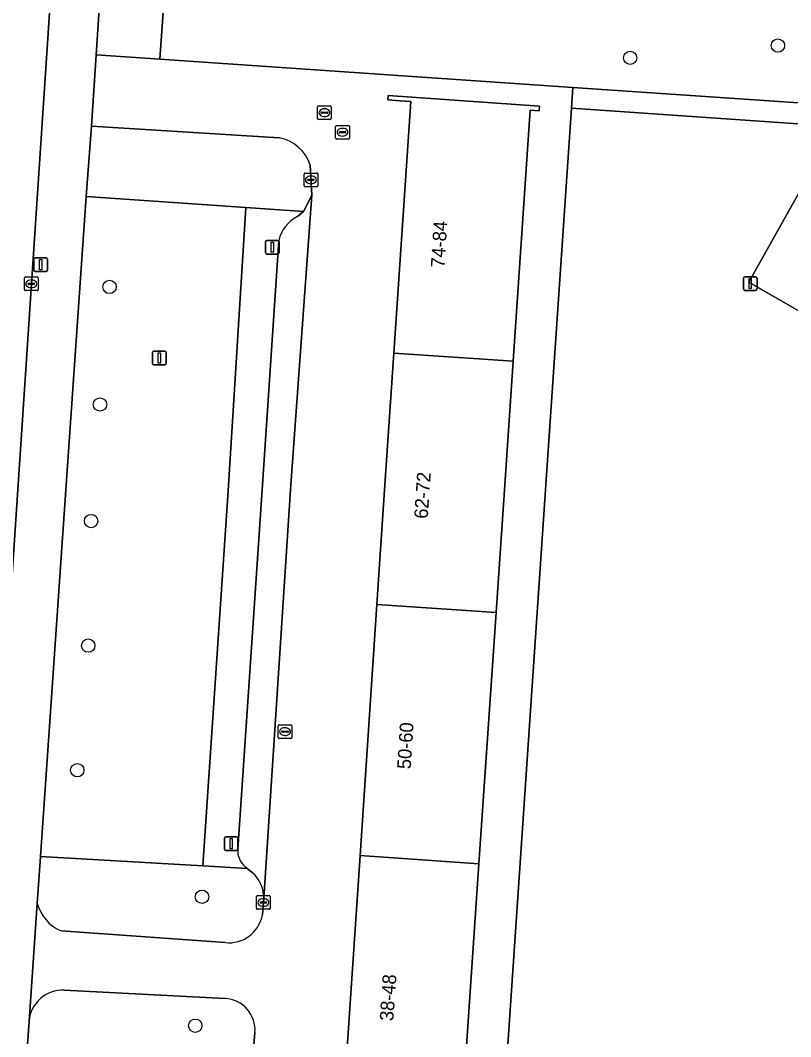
# Model space of a CAD drawing. Extents: x 161848 to 162726, y 385382 to 386521.
# Drawn here: x 162445.2 to 162501.6, y 385460 to 385534.3 of the extents above; entities that cross this region are included whole.
import ezdxf

# ---------------------------------------------------------------- set-up
doc = ezdxf.new("R2010")
doc.units = 0
for name, color, linetype in [('IMGEO_Boom', 7, 'Continuous'), ('IMGEO_Brandkraan', 7, 'Continuous'), ('IMGEO_Groenvoorziening', 7, 'Continuous'), ('IMGEO_Kolk', 7, 'Continuous'), ('IMGEO_Lichtmast', 7, 'Continuous'), ('IMGEO_Pand', 7, 'Continuous'), ('IMGEO_Pand_nummerreeks', 7, 'Continuous'), ('IMGEO_Parkeervlak_open', 7, 'Continuous'), ('IMGEO_Rijbaan_lokaal_gesloten', 7, 'Continuous'), ('IMGEO_Rijbaan_lokaal_open', 7, 'Continuous'), ('IMGEO_Rioolput', 7, 'Continuous'), ('IMGEO_Terreindeel_zand', 7, 'Continuous'), ('IMGEO_Verkeersbordpaal', 7, 'Continuous'), ('IMGEO_Voetpad_open', 7, 'Continuous')]:
    doc.layers.add(name, color=color, linetype=linetype)

msp = doc.modelspace()

# ---------------------------------------------------------------- linework, layer by layer
at = {"layer": 'IMGEO_Boom'}
for centre in [(162500.623, 385532.496), (162489.82, 385531.597), (162451.736, 385514.843), (162451.036, 385506.243), (162450.384, 385497.718), (162450.172, 385488.607), (162449.375, 385479.496), (162458.499, 385470.237), (162458.007, 385460.808)]:
    msp.add_circle(centre, 0.489, dxfattribs=at)
at = {"layer": 'IMGEO_Brandkraan'}
for p, q in [((162468.276, 385525.731), (162468.276, 385526.583)), ((162468.351, 385526.657), (162469.203, 385526.657)), ((162469.277, 385526.583), (162469.277, 385525.731)), ((162468.535, 385526.151), (162468.535, 385526.163)), ((162468.973, 385526.114), (162468.575, 385526.114)), ((162468.578, 385526.2), (162468.976, 385526.2)), ((162468.787, 385525.877), (162468.762, 385525.877)), ((162468.764, 385526.437), (162468.789, 385526.437)), ((162469.019, 385526.163), (162469.019, 385526.151)), ((162469.203, 385525.657), (162468.351, 385525.657))]:
    msp.add_line(p, q, dxfattribs=at)
for points in [[(162468.276, 385525.731), (162468.276, 385526.583)], [(162468.351, 385526.657), (162469.203, 385526.657)], [(162469.277, 385526.583), (162469.277, 385525.731)], [(162469.203, 385525.657), (162468.351, 385525.657)]]:
    msp.add_lwpolyline(points, dxfattribs=at)
for centre, radius, start, end in [((162468.353, 385526.581), 0.0765, 91.55205, 178.44795), ((162468.353, 385526.581), 0.0765, 91.55205, 178.44795), ((162469.201, 385526.581), 0.0765, 1.55205, 88.44795), ((162469.201, 385526.581), 0.0765, 1.55205, 88.44795), ((162468.575, 385526.16), 0.0403, 85.87752, 175.75265), ((162468.572, 385526.15), 0.0366, 178.93798, 274.71019), ((162468.976, 385526.157), 0.043, 264.86636, 352.45326), ((162468.98, 385526.162), 0.0386, 1.73085, 96.63898), ((162468.353, 385525.733), 0.0765, 181.55205, 268.44795), ((162468.353, 385525.733), 0.0765, 181.55205, 268.44795), ((162469.201, 385525.733), 0.0765, 271.55205, 358.44795), ((162469.201, 385525.733), 0.0765, 271.55205, 358.44795)]:
    msp.add_arc(centre, radius, start, end, dxfattribs=at)
for centre, major_axis, ratio, start_param, end_param in [((162468.763, 385526.157), (-0.387, 0.002), 0.722429, 4.712389, 7.853982), ((162468.788, 385526.157), (-0.39, 0.002), 0.717154, 1.570796, 4.712389)]:
    msp.add_ellipse(centre, major_axis=major_axis, ratio=ratio, start_param=start_param, end_param=end_param, dxfattribs=at)
at = {"layer": 'IMGEO_Groenvoorziening'}
for points in [[(162454.648, 385591.147), (162452.933, 385565.323), (162452.649, 385560.747), (162450.744, 385531.817), (162455.419, 385531.5), (162457.472, 385560.354), (162457.863, 385565.85), (162459.643, 385590.86), (162456.232, 385592.147)], [(162457.472, 385560.354), (162455.419, 385531.5), (162485.619, 385529.433), (162500, 385528.449), (162507.432, 385527.947), (162530.647, 385526.38), (162533.646, 385526.394)], [(162545.914, 385523.54), (162543.337, 385523.731), (162511.005, 385526.131), (162512.576, 385525.273), (162511.727, 385523.716), (162517.465, 385520.441), (162510.579, 385508.238), (162498.496, 385515.202), (162504.878, 385526.574), (162500, 385526.911), (162485.517, 385527.913), (162483.623, 385500), (162482.431, 385482.424), (162476.506, 385395.087), (162488.091, 385395.556), (162488.621, 385396.589)], [(162464.139, 385525.753), (162450.405, 385526.588), (162450.031, 385521.458), (162461.707, 385520.661), (162465.911, 385520.366), (162466.531, 385521.555), (162466.414, 385523.772)], [(162465.488, 385519.982), (162465.911, 385520.366), (162461.707, 385520.661), (162460.415, 385499.937), (162458.56, 385472.499), (162461.807, 385472.309), (162461.663, 385472.429)], [(162461.109, 385473.721), (162462.89, 385500), (162464.126, 385518.245)], [(162462.157, 385472.017), (162461.807, 385472.309), (162458.56, 385472.499), (162446.676, 385473.196), (162446.446, 385469.756)], [(162462.922, 385468.908), (162463.011, 385470.132)], [(162448.204, 385467.741), (162460.195, 385466.883)], [(162460.188, 385462.798), (162448.404, 385463.41)], [(162445.849, 385461.151), (162445.688, 385458.726), (162458.022, 385457.834), (162461.314, 385457.562)], [(162462.277, 385459.102), (162462.37, 385460.301)]]:
    msp.add_lwpolyline(points, dxfattribs=at)
msp.add_lwpolyline([(162448.539, 385500), (162446.676, 385473.196), (162458.56, 385472.499), (162460.415, 385499.937), (162461.707, 385520.661), (162450.031, 385521.458)], close=True, dxfattribs=at)
for centre, radius, start, end in [((162463.578, 385522.811), 2.995, 18.70946, 79.19385), ((162466.556, 385517.742), 2.481, 115.49056, 168.3087), ((162462.653, 385473.618), 1.547, 176.19189, 230.22669), ((162460.634, 385470.191), 2.377, 358.57248, 50.17336), ((162449.348, 385470.513), 2.999, 194.62338, 247.58319), ((162460.457, 385469.379), 2.51, 264.01062, 349.18264), ((162448.302, 385460.951), 2.461, 87.62337, 175.33956), ((162460.069, 385460.492), 2.309, 355.2525, 87.04458)]:
    msp.add_arc(centre, radius, start, end, dxfattribs=at)
at = {"layer": 'IMGEO_Kolk'}
for p, q in [((162465.967, 385522.246), (162465.967, 385523.098)), ((162466.042, 385523.172), (162466.894, 385523.172)), ((162466.455, 385522.952), (162466.48, 385522.952)), ((162466.968, 385523.098), (162466.968, 385522.246)), ((162466.894, 385522.172), (162466.042, 385522.172)), ((162466.226, 385522.666), (162466.226, 385522.678)), ((162466.664, 385522.629), (162466.266, 385522.629)), ((162466.269, 385522.715), (162466.667, 385522.715)), ((162466.478, 385522.392), (162466.453, 385522.392)), ((162466.71, 385522.678), (162466.71, 385522.666)), ((162445.508, 385514.644), (162445.508, 385515.496)), ((162445.583, 385515.57), (162446.435, 385515.57)), ((162446.509, 385515.496), (162446.509, 385514.644)), ((162445.767, 385515.064), (162445.767, 385515.076)), ((162446.205, 385515.027), (162445.807, 385515.027)), ((162445.81, 385515.113), (162446.208, 385515.113)), ((162446.019, 385514.79), (162445.994, 385514.79)), ((162445.996, 385515.35), (162446.021, 385515.35)), ((162446.251, 385515.076), (162446.251, 385515.064)), ((162446.435, 385514.57), (162445.583, 385514.57)), ((162462.486, 385469.395), (162462.486, 385470.247)), ((162462.561, 385470.321), (162463.413, 385470.321)), ((162462.974, 385470.101), (162462.999, 385470.101)), ((162463.487, 385470.247), (162463.487, 385469.395)), ((162463.413, 385469.321), (162462.561, 385469.321)), ((162462.745, 385469.815), (162462.745, 385469.827)), ((162463.183, 385469.778), (162462.785, 385469.778)), ((162462.788, 385469.864), (162463.186, 385469.864)), ((162462.997, 385469.541), (162462.972, 385469.541)), ((162463.229, 385469.827), (162463.229, 385469.815))]:
    msp.add_line(p, q, dxfattribs=at)
for points in [[(162465.967, 385522.246), (162465.967, 385523.098)], [(162466.042, 385523.172), (162466.894, 385523.172)], [(162466.968, 385523.098), (162466.968, 385522.246)], [(162466.894, 385522.172), (162466.042, 385522.172)], [(162445.508, 385514.644), (162445.508, 385515.496)], [(162445.583, 385515.57), (162446.435, 385515.57)], [(162446.509, 385515.496), (162446.509, 385514.644)], [(162446.435, 385514.57), (162445.583, 385514.57)], [(162462.486, 385469.395), (162462.486, 385470.247)], [(162462.561, 385470.321), (162463.413, 385470.321)], [(162463.487, 385470.247), (162463.487, 385469.395)], [(162463.413, 385469.321), (162462.561, 385469.321)]]:
    msp.add_lwpolyline(points, dxfattribs=at)
for centre, radius, start, end in [((162466.044, 385523.096), 0.0765, 91.55205, 178.44795), ((162466.044, 385523.096), 0.0765, 91.55205, 178.44795), ((162466.892, 385523.096), 0.0765, 1.55205, 88.44795), ((162466.892, 385523.096), 0.0765, 1.55205, 88.44795), ((162466.044, 385522.248), 0.0765, 181.55205, 268.44795), ((162466.044, 385522.248), 0.0765, 181.55205, 268.44795), ((162466.266, 385522.675), 0.0403, 85.87752, 175.75265), ((162466.263, 385522.665), 0.0366, 178.93798, 274.71019), ((162466.667, 385522.672), 0.043, 264.86636, 352.45326), ((162466.671, 385522.677), 0.0386, 1.73085, 96.63898), ((162466.892, 385522.248), 0.0765, 271.55205, 358.44795), ((162466.892, 385522.248), 0.0765, 271.55205, 358.44795), ((162445.585, 385515.494), 0.0765, 91.55205, 178.44795), ((162445.585, 385515.494), 0.0765, 91.55205, 178.44795), ((162446.433, 385515.494), 0.0765, 1.55205, 88.44795), ((162446.433, 385515.494), 0.0765, 1.55205, 88.44795), ((162445.585, 385514.646), 0.0765, 181.55205, 268.44795), ((162445.585, 385514.646), 0.0765, 181.55205, 268.44795), ((162445.807, 385515.073), 0.0403, 85.87752, 175.75265), ((162445.804, 385515.063), 0.0366, 178.93798, 274.71019), ((162446.208, 385515.07), 0.043, 264.86636, 352.45326), ((162446.212, 385515.075), 0.0386, 1.73085, 96.63898), ((162446.433, 385514.646), 0.0765, 271.55205, 358.44795), ((162446.433, 385514.646), 0.0765, 271.55205, 358.44795), ((162462.563, 385470.245), 0.0765, 91.55205, 178.44795), ((162462.563, 385470.245), 0.0765, 91.55205, 178.44795), ((162463.411, 385470.245), 0.0765, 1.55205, 88.44795), ((162463.411, 385470.245), 0.0765, 1.55205, 88.44795), ((162462.563, 385469.397), 0.0765, 181.55205, 268.44795), ((162462.563, 385469.397), 0.0765, 181.55205, 268.44795), ((162462.785, 385469.824), 0.0403, 85.87752, 175.75265), ((162462.782, 385469.814), 0.0366, 178.93798, 274.71019), ((162463.186, 385469.821), 0.043, 264.86636, 352.45326), ((162463.19, 385469.826), 0.0386, 1.73085, 96.63898), ((162463.411, 385469.397), 0.0765, 271.55205, 358.44795), ((162463.411, 385469.397), 0.0765, 271.55205, 358.44795)]:
    msp.add_arc(centre, radius, start, end, dxfattribs=at)
for centre, major_axis, ratio, start_param, end_param in [((162466.454, 385522.672), (-0.387, 0.002), 0.722429, 4.712389, 7.853982), ((162466.479, 385522.672), (-0.39, 0.002), 0.717154, 1.570796, 4.712389), ((162445.995, 385515.07), (-0.387, 0.002), 0.722429, 4.712389, 7.853982), ((162446.02, 385515.07), (-0.39, 0.002), 0.717154, 1.570796, 4.712389), ((162462.973, 385469.821), (-0.387, 0.002), 0.722429, 4.712389, 7.853982), ((162462.998, 385469.821), (-0.39, 0.002), 0.717154, 1.570796, 4.712389)]:
    msp.add_ellipse(centre, major_axis=major_axis, ratio=ratio, start_param=start_param, end_param=end_param, dxfattribs=at)
at = {"layer": 'IMGEO_Lichtmast'}
for p, q in [((162463.148, 385517.348), (162463.148, 385518.148)), ((162463.148, 385518.148), (162463.148, 385517.348)), ((162463.248, 385518.248), (162464.038, 385518.248)), ((162464.038, 385518.248), (162463.248, 385518.248)), ((162464.138, 385518.148), (162464.138, 385517.348)), ((162464.138, 385517.348), (162464.138, 385518.148)), ((162446.201, 385516.062), (162446.201, 385516.862)), ((162446.201, 385516.862), (162446.201, 385516.062)), ((162446.301, 385516.962), (162447.091, 385516.962)), ((162447.091, 385516.962), (162446.301, 385516.962)), ((162447.191, 385516.862), (162447.191, 385516.062)), ((162447.191, 385516.062), (162447.191, 385516.862)), ((162464.038, 385517.248), (162463.248, 385517.248)), ((162463.248, 385517.248), (162464.038, 385517.248)), ((162447.091, 385515.962), (162446.301, 385515.962)), ((162446.301, 385515.962), (162447.091, 385515.962)), ((162460.139, 385473.723), (162460.139, 385474.523)), ((162460.139, 385474.523), (162460.139, 385473.723)), ((162460.239, 385474.623), (162461.029, 385474.623)), ((162461.029, 385474.623), (162460.239, 385474.623)), ((162461.129, 385474.523), (162461.129, 385473.723)), ((162461.129, 385473.723), (162461.129, 385474.523)), ((162461.029, 385473.623), (162460.239, 385473.623)), ((162460.239, 385473.623), (162461.029, 385473.623))]:
    msp.add_line(p, q, dxfattribs=at)
for points in [[(162463.568, 385518.123), (162463.718, 385518.123), (162463.718, 385517.373), (162463.568, 385517.373), (162463.568, 385518.123)], [(162446.621, 385516.837), (162446.771, 385516.837), (162446.771, 385516.087), (162446.621, 385516.087), (162446.621, 385516.837)], [(162460.559, 385474.498), (162460.709, 385474.498), (162460.709, 385473.748), (162460.559, 385473.748), (162460.559, 385474.498)]]:
    msp.add_lwpolyline(points, dxfattribs=at)
for centre, start, end in [((162463.248, 385518.148), 90, 180), ((162463.248, 385518.148), 90, 180), ((162464.038, 385518.148), 0, 90), ((162464.038, 385518.148), 360, 90), ((162446.301, 385516.862), 90, 180), ((162446.301, 385516.862), 90, 180), ((162447.091, 385516.862), 0, 90), ((162447.091, 385516.862), 360, 90), ((162463.248, 385517.348), 180, 270), ((162463.248, 385517.348), 180, 270), ((162464.038, 385517.348), 270, 0), ((162464.038, 385517.348), 270, 0), ((162446.301, 385516.062), 180, 270), ((162446.301, 385516.062), 180, 270), ((162447.091, 385516.062), 270, 0), ((162447.091, 385516.062), 270, 0), ((162460.239, 385474.523), 90, 180), ((162460.239, 385474.523), 90, 180), ((162461.029, 385474.523), 0, 90), ((162461.029, 385474.523), 360, 90), ((162460.239, 385473.723), 180, 270), ((162460.239, 385473.723), 180, 270), ((162461.029, 385473.723), 270, 0), ((162461.029, 385473.723), 270, 0)]:
    msp.add_arc(centre, 0.1, start, end, dxfattribs=at)
at = {"layer": 'IMGEO_Pand'}
for points in [[(162473.772, 385528.397), (162472.532, 385509.995), (162481.258, 385509.402), (162482.508, 385527.775), (162483.158, 385527.73), (162483.182, 385528.074), (162472.117, 385528.841), (162472.095, 385528.514), (162472.999, 385528.451)], [(162471.859, 385500), (162471.295, 385491.621), (162480.009, 385491.029), (162480.619, 385500), (162481.258, 385509.402), (162472.532, 385509.995)], [(162470.057, 385473.247), (162478.76, 385472.656), (162480.009, 385491.029), (162471.295, 385491.621)], [(162468.819, 385454.873), (162477.51, 385454.282), (162478.76, 385472.656), (162470.057, 385473.247)]]:
    msp.add_lwpolyline(points, close=True, dxfattribs=at)
at = {"layer": 'IMGEO_Parkeervlak_open'}
for points in [[(162463.011, 385470.132), (162464.984, 385500), (162465.008, 385500.369), (162466.531, 385521.555), (162465.911, 385520.366), (162465.488, 385519.982)], [(162464.126, 385518.245), (162462.89, 385500), (162461.109, 385473.721)], [(162461.663, 385472.429), (162461.807, 385472.309), (162462.157, 385472.017)]]:
    msp.add_lwpolyline(points, dxfattribs=at)
for centre, radius, start, end in [((162466.556, 385517.742), 2.481, 115.49056, 168.3087), ((162462.653, 385473.618), 1.547, 176.19189, 230.22669), ((162460.634, 385470.191), 2.377, 358.57248, 50.17336)]:
    msp.add_arc(centre, radius, start, end, dxfattribs=at)
at = {"layer": 'IMGEO_Rijbaan_lokaal_gesloten'}
msp.add_lwpolyline([(162442.399, 385460.482), (162442.465, 385461.839), (162450.162, 385577.468)], dxfattribs=at)
at = {"layer": 'IMGEO_Rijbaan_lokaal_open'}
for points in [[(162482.431, 385482.424), (162483.623, 385500), (162485.517, 385527.913), (162485.619, 385529.433), (162455.419, 385531.5), (162450.744, 385531.817), (162450.405, 385526.588), (162464.139, 385525.753)], [(162466.414, 385523.772), (162466.531, 385521.555), (162465.008, 385500.369), (162464.984, 385500), (162463.011, 385470.132), (162462.922, 385468.908)], [(162462.37, 385460.301), (162462.277, 385459.102), (162462.235, 385458.558), (162458.175, 385399.31), (162457.836, 385394.534), (162462.968, 385394.635), (162463.18, 385398.467), (162475.007, 385397.387), (162474.868, 385395.02), (162476.506, 385395.087), (162482.431, 385482.424)], [(162446.446, 385469.756), (162445.849, 385461.151)], [(162460.195, 385466.883), (162448.204, 385467.741)], [(162448.404, 385463.41), (162460.188, 385462.798)]]:
    msp.add_lwpolyline(points, dxfattribs=at)
msp.add_lwpolyline([(162470.057, 385473.247), (162471.295, 385491.621), (162471.859, 385500), (162472.532, 385509.995), (162473.772, 385528.397), (162472.999, 385528.451), (162472.095, 385528.514), (162472.117, 385528.841), (162483.182, 385528.074), (162483.158, 385527.73), (162482.508, 385527.775), (162481.258, 385509.402), (162480.619, 385500), (162480.009, 385491.029), (162478.76, 385472.656), (162477.51, 385454.282), (162476.261, 385435.909), (162475.011, 385417.536), (162473.762, 385399.163), (162465.106, 385399.742), (162466.344, 385418.126), (162467.582, 385436.499), (162468.819, 385454.873)], close=True, dxfattribs=at)
for centre, radius, start, end in [((162463.578, 385522.811), 2.995, 18.70946, 79.19385), ((162449.348, 385470.513), 2.999, 194.62338, 247.58319), ((162460.457, 385469.379), 2.51, 264.01062, 349.18264), ((162448.302, 385460.951), 2.461, 87.62337, 175.33956), ((162460.069, 385460.492), 2.309, 355.2525, 87.04458)]:
    msp.add_arc(centre, radius, start, end, dxfattribs=at)
at = {"layer": 'IMGEO_Rioolput'}
for p, q in [((162466.955, 385527.16), (162466.955, 385528.012)), ((162467.03, 385528.086), (162467.882, 385528.086)), ((162467.956, 385528.012), (162467.956, 385527.16)), ((162467.214, 385527.58), (162467.214, 385527.592)), ((162467.652, 385527.543), (162467.254, 385527.543)), ((162467.257, 385527.629), (162467.655, 385527.629)), ((162467.466, 385527.306), (162467.441, 385527.306)), ((162467.443, 385527.866), (162467.468, 385527.866)), ((162467.698, 385527.592), (162467.698, 385527.58)), ((162467.882, 385527.086), (162467.03, 385527.086)), ((162464.073, 385481.89), (162464.073, 385482.742)), ((162464.148, 385482.816), (162465, 385482.816)), ((162465.074, 385482.742), (162465.074, 385481.89)), ((162464.332, 385482.31), (162464.332, 385482.322)), ((162464.77, 385482.273), (162464.372, 385482.273)), ((162464.375, 385482.359), (162464.773, 385482.359)), ((162464.584, 385482.036), (162464.559, 385482.036)), ((162464.561, 385482.596), (162464.586, 385482.596)), ((162464.816, 385482.322), (162464.816, 385482.31)), ((162465, 385481.816), (162464.148, 385481.816))]:
    msp.add_line(p, q, dxfattribs=at)
for points in [[(162466.955, 385527.16), (162466.955, 385528.012)], [(162467.03, 385528.086), (162467.882, 385528.086)], [(162467.956, 385528.012), (162467.956, 385527.16)], [(162467.882, 385527.086), (162467.03, 385527.086)], [(162464.073, 385481.89), (162464.073, 385482.742)], [(162464.148, 385482.816), (162465, 385482.816)], [(162465.074, 385482.742), (162465.074, 385481.89)], [(162465, 385481.816), (162464.148, 385481.816)]]:
    msp.add_lwpolyline(points, dxfattribs=at)
for centre, radius, start, end in [((162467.032, 385528.01), 0.0765, 91.55205, 178.44795), ((162467.032, 385528.01), 0.0765, 91.55205, 178.44795), ((162467.88, 385528.01), 0.0765, 1.55205, 88.44795), ((162467.88, 385528.01), 0.0765, 1.55205, 88.44795), ((162467.254, 385527.589), 0.0403, 85.87752, 175.75265), ((162467.251, 385527.579), 0.0366, 178.93798, 274.71019), ((162467.655, 385527.586), 0.043, 264.86636, 352.45326), ((162467.659, 385527.591), 0.0386, 1.73085, 96.63898), ((162467.032, 385527.162), 0.0765, 181.55205, 268.44795), ((162467.032, 385527.162), 0.0765, 181.55205, 268.44795), ((162467.88, 385527.162), 0.0765, 271.55205, 358.44795), ((162467.88, 385527.162), 0.0765, 271.55205, 358.44795), ((162464.15, 385482.74), 0.0765, 91.55205, 178.44795), ((162464.15, 385482.74), 0.0765, 91.55205, 178.44795), ((162464.998, 385482.74), 0.0765, 1.55205, 88.44795), ((162464.998, 385482.74), 0.0765, 1.55205, 88.44795), ((162464.372, 385482.319), 0.0403, 85.87752, 175.75265), ((162464.369, 385482.309), 0.0366, 178.93798, 274.71019), ((162464.773, 385482.316), 0.043, 264.86636, 352.45326), ((162464.777, 385482.321), 0.0386, 1.73085, 96.63898), ((162464.15, 385481.892), 0.0765, 181.55205, 268.44795), ((162464.15, 385481.892), 0.0765, 181.55205, 268.44795), ((162464.998, 385481.892), 0.0765, 271.55205, 358.44795), ((162464.998, 385481.892), 0.0765, 271.55205, 358.44795)]:
    msp.add_arc(centre, radius, start, end, dxfattribs=at)
for centre, major_axis, ratio, start_param, end_param in [((162467.442, 385527.586), (-0.387, 0.002), 0.722429, 4.712389, 7.853982), ((162467.467, 385527.586), (-0.39, 0.002), 0.717154, 1.570796, 4.712389), ((162464.56, 385482.316), (-0.387, 0.002), 0.722429, 4.712389, 7.853982), ((162464.585, 385482.316), (-0.39, 0.002), 0.717154, 1.570796, 4.712389)]:
    msp.add_ellipse(centre, major_axis=major_axis, ratio=ratio, start_param=start_param, end_param=end_param, dxfattribs=at)
at = {"layer": 'IMGEO_Terreindeel_zand'}
msp.add_lwpolyline([(162511.727, 385523.716), (162511.718, 385523.721), (162509.058, 385525.239), (162509.056, 385525.24), (162506.975, 385526.429), (162504.878, 385526.574), (162498.496, 385515.202), (162510.579, 385508.238), (162517.465, 385520.441)], close=True, dxfattribs=at)
at = {"layer": 'IMGEO_Verkeersbordpaal'}
for p, q in [((162498.109, 385514.691), (162498.109, 385515.491)), ((162498.109, 385515.491), (162498.109, 385514.691)), ((162498.209, 385515.591), (162498.999, 385515.591)), ((162498.999, 385515.591), (162498.209, 385515.591)), ((162499.099, 385515.491), (162499.099, 385514.691)), ((162499.099, 385514.691), (162499.099, 385515.491)), ((162498.999, 385514.591), (162498.209, 385514.591)), ((162498.209, 385514.591), (162498.999, 385514.591)), ((162454.882, 385509.249), (162454.882, 385510.049)), ((162454.882, 385510.049), (162454.882, 385509.249)), ((162454.982, 385510.149), (162455.772, 385510.149)), ((162455.772, 385510.149), (162454.982, 385510.149)), ((162455.872, 385510.049), (162455.872, 385509.249)), ((162455.872, 385509.249), (162455.872, 385510.049)), ((162455.772, 385509.149), (162454.982, 385509.149)), ((162454.982, 385509.149), (162455.772, 385509.149))]:
    msp.add_line(p, q, dxfattribs=at)
for points in [[(162498.529, 385515.466), (162498.679, 385515.466), (162498.679, 385514.716), (162498.529, 385514.716), (162498.529, 385515.466)], [(162455.302, 385510.024), (162455.452, 385510.024), (162455.452, 385509.274), (162455.302, 385509.274), (162455.302, 385510.024)]]:
    msp.add_lwpolyline(points, dxfattribs=at)
for centre, start, end in [((162498.209, 385515.491), 90, 180), ((162498.209, 385515.491), 90, 180), ((162498.999, 385515.491), 0, 90), ((162498.999, 385515.491), 360, 90), ((162498.209, 385514.691), 180, 270), ((162498.209, 385514.691), 180, 270), ((162498.999, 385514.691), 270, 0), ((162498.999, 385514.691), 270, 0), ((162454.982, 385510.049), 90, 180), ((162454.982, 385510.049), 90, 180), ((162455.772, 385510.049), 0, 90), ((162455.772, 385510.049), 360, 90), ((162454.982, 385509.249), 180, 270), ((162454.982, 385509.249), 180, 270), ((162455.772, 385509.249), 270, 0), ((162455.772, 385509.249), 270, 0)]:
    msp.add_arc(centre, 0.1, start, end, dxfattribs=at)
at = {"layer": 'IMGEO_Voetpad_open'}
msp.add_lwpolyline([(162442.256, 385407.756), (162443.737, 385429.387), (162445.688, 385458.726), (162445.849, 385461.151), (162446.446, 385469.756), (162446.676, 385473.196), (162448.539, 385500), (162450.031, 385521.458), (162450.405, 385526.588), (162450.744, 385531.817), (162452.649, 385560.747), (162452.933, 385565.323), (162454.648, 385591.147), (162455.021, 385596.06), (162455.065, 385596.685), (162455.738, 385606.152), (162455.776, 385606.687), (162452.208, 385607.27), (162451.787, 385601.362), (162451.635, 385598.888), (162450.352, 385579.883), (162450.162, 385577.468), (162442.465, 385461.839), (162442.399, 385460.482)], dxfattribs=at)
msp.add_lwpolyline([(162507.432, 385527.947), (162500, 385528.449), (162485.619, 385529.433), (162485.517, 385527.913), (162500, 385526.911), (162504.878, 385526.574), (162506.975, 385526.429), (162507.329, 385526.404)], close=True, dxfattribs=at)

# ---------------------------------------------------------------- texts
at = {"layer": 'IMGEO_Pand_nummerreeks'}
for s, rotation, p in [('74-84', 86.35744, (162476.23, 385516.22)), ('62-72', 86.0961, (162475.007, 385497.862)), ('50-60', 86.37661, (162473.764, 385479.55)), ('38-48', 86.08586, (162472.491, 385461.124))]:
    msp.add_text(s, height=1, rotation=rotation, dxfattribs=at).set_placement(p)

doc.saveas('drawing.dxf')
